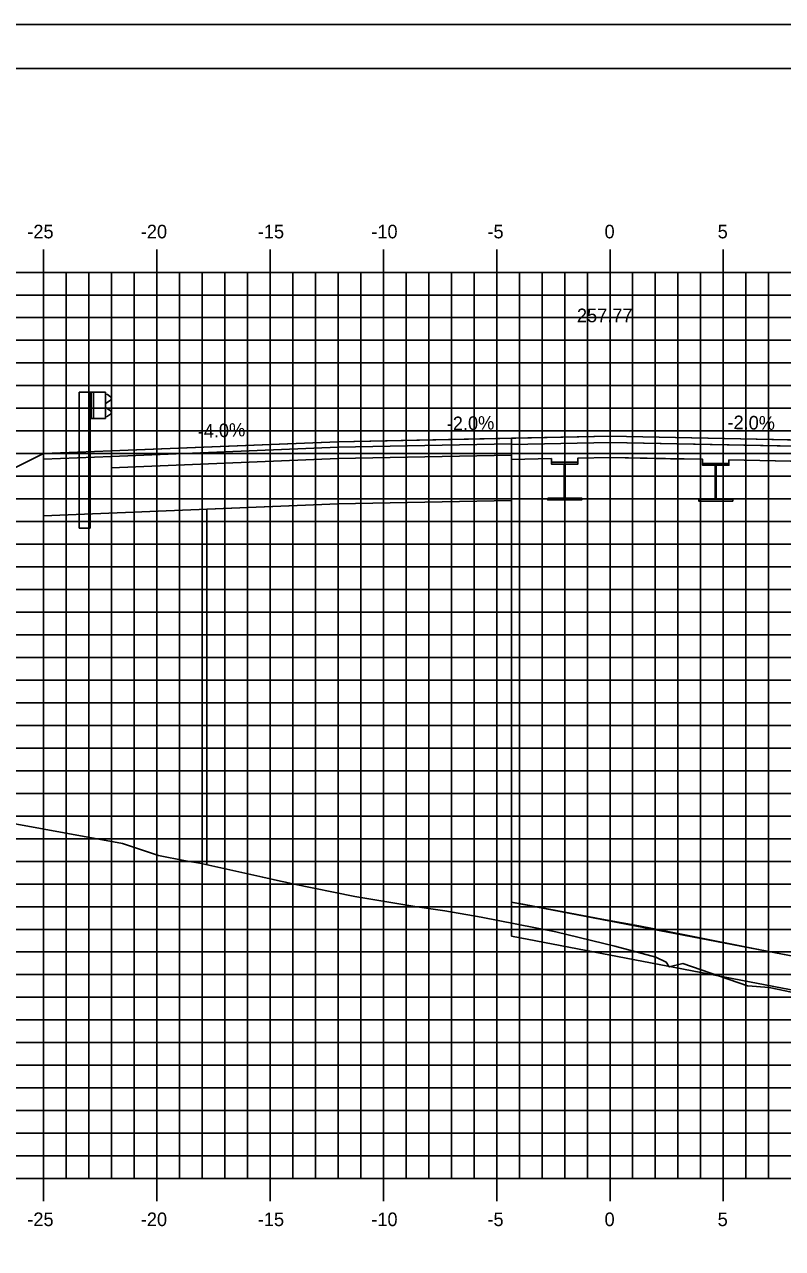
# Model space of a CAD drawing. Extents: x -22 to 1480, y -1511 to 8.
# Drawn here: x 700.4 to 733.8, y -128.6 to -74.5 of the extents above; entities that cross this region are included whole.
import ezdxf

# ---------------------------------------------------------------- set-up
doc = ezdxf.new("R2010")
doc.units = 0
for name, color, linetype in [('ANNOTATION', 7, 'Continuous'), ('BORDER', 7, 'Continuous'), ('D_Bridge_Superstructure', 7, 'Continuous'), ('D_Bridge_Superstructure_Slab', 7, 'Continuous'), ('D_Bridge_Wingwall', 7, 'Continuous'), ('D_Guardrail_Beam_Rt', 7, 'Continuous'), ('D_Roadway_Centerline', 7, 'Continuous'), ('D_Roadway_Centerline_Text', 7, 'Continuous'), ('D_Roadway_Edge_Shoulder', 7, 'Continuous'), ('D_Roadway_Edge_TW', 7, 'Continuous'), ('D_Roadway_Pavement', 7, 'Continuous'), ('D_Roadway_SlopeLines', 7, 'Continuous'), ('D_Roadway_SubGrade', 7, 'Continuous'), ('H_V ANNOTATION', 7, 'Continuous'), ('MAJOR', 7, 'Continuous'), ('MINOR', 7, 'Continuous'), ('PLOT BOUNDARY', 7, 'Continuous'), ('S_Roadway_Centerline', 7, 'Continuous')]:
    doc.layers.add(name, color=color, linetype=linetype)

msp = doc.modelspace()

# ---------------------------------------------------------------- linework, layer by layer
at = {"layer": 'BORDER'}
msp.add_line((811.209, -76.466), (651.209, -76.466), dxfattribs=at)
at = {"layer": 'D_Bridge_Superstructure'}
for p, q in [((724.792, -93.844), (723.626, -93.844)), ((723.626, -93.844), (723.626, -93.928)), ((724.23, -93.928), (724.188, -93.928)), ((724.23, -93.928), (724.188, -93.928)), ((724.23, -93.928), (724.792, -93.928)), ((724.792, -93.928), (724.792, -93.844)), ((731.459, -93.898), (730.292, -93.898)), ((730.292, -93.898), (730.292, -93.981)), ((730.897, -93.981), (730.855, -93.981)), ((730.897, -93.981), (730.855, -93.981)), ((730.897, -93.981), (731.459, -93.981)), ((731.459, -93.981), (731.459, -93.898)), ((724.188, -95.428), (723.459, -95.428)), ((723.459, -95.428), (723.459, -95.511)), ((724.188, -95.428), (723.459, -95.428)), ((724.23, -95.428), (724.188, -95.428)), ((724.23, -95.428), (724.188, -95.428)), ((730.855, -95.481), (730.126, -95.481)), ((730.126, -95.481), (730.126, -95.564)), ((730.855, -95.481), (730.126, -95.481)), ((730.897, -95.481), (730.855, -95.481)), ((730.897, -95.481), (730.855, -95.481))]:
    msp.add_line(p, q, dxfattribs=at)
for points in [[(723.626, -93.844), (724.792, -93.844), (724.792, -93.928), (723.626, -93.928)], [(724.188, -93.928), (724.23, -93.928), (724.23, -95.428), (724.188, -95.428)], [(730.292, -93.898), (731.459, -93.898), (731.459, -93.981), (730.292, -93.981)], [(730.855, -93.981), (730.897, -93.981), (730.897, -95.481), (730.855, -95.481)], [(723.459, -95.428), (724.959, -95.428), (724.959, -95.511), (723.459, -95.511)], [(730.126, -95.481), (731.626, -95.481), (731.626, -95.564), (730.126, -95.564)]]:
    msp.add_lwpolyline(points, close=True, dxfattribs=at)
for points in [[(724.23, -93.928), (724.792, -93.928), (724.792, -93.844), (723.626, -93.844), (723.626, -93.928), (724.188, -93.928), (724.23, -93.928)], [(723.626, -93.928), (724.188, -93.928), (724.23, -93.928)], [(724.188, -93.928), (724.188, -95.428), (724.23, -95.428), (724.23, -93.928)], [(724.188, -93.928), (724.188, -95.428), (724.23, -95.428), (724.23, -93.928)], [(730.897, -93.981), (731.459, -93.981), (731.459, -93.898), (730.292, -93.898), (730.292, -93.981), (730.855, -93.981), (730.897, -93.981)], [(730.292, -93.981), (730.855, -93.981), (730.897, -93.981)], [(730.855, -93.981), (730.855, -95.481), (730.897, -95.481), (730.897, -93.981)], [(730.855, -93.981), (730.855, -95.481), (730.897, -95.481), (730.897, -93.981)], [(723.459, -95.428), (723.459, -95.511), (724.959, -95.511), (724.959, -95.428), (724.23, -95.428)], [(723.459, -95.511), (724.959, -95.511), (724.959, -95.428), (724.23, -95.428)], [(730.126, -95.481), (730.126, -95.564), (731.626, -95.564), (731.626, -95.481), (730.897, -95.481)], [(730.126, -95.564), (731.626, -95.564), (731.626, -95.481), (730.897, -95.481)]]:
    msp.add_lwpolyline(points, dxfattribs=at)
at = {"layer": 'D_Bridge_Superstructure_Slab'}
msp.add_line((726.209, -93.638), (726.209, -93.638), dxfattribs=at)
for points in [[(721.855, -92.787), (726.209, -92.7), (744.231, -93.061), (744.209, -93.331), (726.209, -92.971), (721.855, -93.058)], [(745.376, -93.354), (726.209, -92.971), (721.855, -93.058)], [(745.376, -93.354), (726.209, -92.971), (721.855, -93.058)], [(721.855, -93.725), (723.626, -93.689), (723.626, -93.844), (724.792, -93.844), (724.792, -93.666), (726.209, -93.638), (727.542, -93.664), (728.876, -93.691), (730.292, -93.719), (730.292, -93.898), (731.459, -93.898), (731.459, -93.743), (735.542, -93.824)], [(723.626, -93.689), (721.855, -93.725)], [(724.792, -93.666), (724.792, -93.844), (723.626, -93.844), (723.626, -93.689)], [(730.292, -93.719), (726.209, -93.638), (724.792, -93.666)], [(730.292, -93.719), (730.292, -93.898), (731.459, -93.898), (731.459, -93.743)], [(736.959, -93.853), (731.459, -93.743)]]:
    msp.add_lwpolyline(points, dxfattribs=at)
at = {"layer": 'D_Bridge_Wingwall'}
msp.add_lwpolyline([(721.855, -114.194), (721.855, -95.537), (714.209, -95.69), (708.412, -95.922), (708.412, -111.617)], dxfattribs=at)
at = {"layer": 'D_Guardrail_Beam_Rt'}
for p, q in [((702.78, -90.757), (702.78, -96.757)), ((703.25, -90.757), (702.78, -90.757)), ((703.938, -90.757), (703.25, -90.757)), ((703.25, -90.757), (703.25, -91.923)), ((703.313, -90.757), (703.313, -91.923)), ((703.417, -90.757), (703.417, -91.923)), ((703.938, -91.923), (703.938, -90.757)), ((703.938, -90.84), (704.012, -90.855)), ((703.942, -91.305), (703.942, -91.375)), ((704.171, -91.104), (703.976, -91.241)), ((704.028, -90.861), (704.171, -90.961)), ((704.012, -91.826), (703.938, -91.84)), ((703.976, -91.44), (704.171, -91.576)), ((704.171, -91.719), (704.028, -91.819)), ((703.25, -91.923), (703.938, -91.923)), ((703.271, -96.757), (703.271, -91.923)), ((703.271, -96.757), (702.78, -96.757))]:
    msp.add_line(p, q, dxfattribs=at)
for centre, major_axis, start_param, end_param in [((704.021, -91.305), (-0.0789, 0), 5.323254, 6.283185), ((704.004, -90.895), (0.0417, 0), 0.959931, 1.376053), ((704.121, -91.033), (0.0877, 0), 5.323254, 7.243116), ((704.021, -91.375), (-0.0789, 0), 6.283185, 7.243116), ((704.004, -91.785), (0.0417, 0), 4.907132, 5.323254), ((704.121, -91.647), (0.0877, 0), 5.323254, 7.243116)]:
    msp.add_ellipse(centre, major_axis=major_axis, ratio=0.995501, start_param=start_param, end_param=end_param, dxfattribs=at)
at = {"layer": 'D_Roadway_Centerline'}
msp.add_line((701.209, -93.46), (697.091, -95.519), dxfattribs=at)
for points in [[(701.209, -93.46), (702.709, -93.4), (704.209, -93.34), (709.009, -93.148), (714.209, -92.94), (719.969, -92.825), (726.209, -92.7), (731.969, -92.815), (738.209, -92.94), (739.835, -92.973), (742.467, -93.025), (743.371, -93.043), (744.231, -93.061)], [(721.855, -113.261), (722.095, -113.306), (722.193, -113.324), (725.854, -114.013), (727.479, -114.318), (729.585, -114.73), (732.765, -115.352), (734.514, -115.697), (738.052, -115.435), (739.911, -115.297), (743.338, -115.044), (745.011, -114.942), (748.624, -114.722), (748.947, -114.702), (749.89, -114.645), (752.884, -114.754), (753.911, -114.789), (756.909, -114.855), (759.197, -114.913), (763.898, -115.022), (764.484, -115.034), (765.554, -115.061), (769.77, -115.176)]]:
    msp.add_lwpolyline(points, dxfattribs=at)
at = {"layer": 'D_Roadway_Edge_Shoulder'}
msp.add_lwpolyline([(714.209, -92.94), (704.209, -93.34), (704.209, -93.34), (701.209, -93.46), (701.209, -93.71), (704.209, -93.59), (704.209, -93.59), (714.209, -93.19)], close=True, dxfattribs=at)
at = {"layer": 'D_Roadway_Edge_TW'}
msp.add_lwpolyline([(721.855, -92.787), (714.209, -92.94), (714.209, -93.19), (721.855, -93.037)], dxfattribs=at)
at = {"layer": 'D_Roadway_Pavement'}
msp.add_lwpolyline([(714.209, -93.19), (704.209, -93.59), (704.209, -93.59), (704.209, -94.09), (714.209, -93.69), (714.209, -93.19)], dxfattribs=at)
at = {"layer": 'D_Roadway_SlopeLines'}
msp.add_lwpolyline([(749.89, -114.645), (734.514, -115.697), (721.855, -113.261), (721.855, -114.761), (734.514, -117.197), (749.89, -116.145)], close=True, dxfattribs=at)
msp.add_lwpolyline([(734.514, -115.697), (721.855, -113.261)], dxfattribs=at)
msp.add_lwpolyline([(734.514, -115.697), (721.855, -113.261)], dxfattribs=at)
at = {"layer": 'D_Roadway_SubGrade'}
msp.add_line((721.855, -95.537), (721.855, -92.787), dxfattribs=at)
msp.add_lwpolyline([(714.209, -93.69), (704.209, -94.09), (704.209, -93.59), (701.209, -93.71), (701.209, -93.46), (701.209, -96.21), (714.209, -95.69)], close=True, dxfattribs=at)
msp.add_lwpolyline([(721.855, -93.537), (714.209, -93.69), (714.209, -95.69), (721.855, -95.537)], dxfattribs=at)
at = {"layer": 'MAJOR'}
for p, q in [((701.209, -84.464), (701.209, -85.466)), ((706.209, -84.464), (706.209, -85.466)), ((711.209, -84.464), (711.209, -85.466)), ((716.209, -84.464), (716.209, -85.466)), ((721.209, -84.464), (721.209, -85.466)), ((726.209, -84.464), (726.209, -85.466)), ((731.209, -84.464), (731.209, -85.466)), ((656.209, -85.466), (796.209, -85.466)), ((656.209, -85.466), (796.209, -85.466)), ((701.209, -125.466), (701.209, -85.466)), ((706.209, -125.466), (706.209, -85.466)), ((711.209, -125.466), (711.209, -85.466)), ((716.209, -125.466), (716.209, -85.466)), ((721.209, -125.466), (721.209, -85.466)), ((726.209, -125.466), (726.209, -85.466)), ((731.209, -125.466), (731.209, -85.466)), ((656.209, -90.466), (796.209, -90.466)), ((656.209, -95.466), (796.209, -95.466)), ((656.209, -100.466), (796.209, -100.466)), ((656.209, -105.466), (796.209, -105.466)), ((656.209, -110.466), (796.209, -110.466)), ((656.209, -115.466), (796.209, -115.466)), ((656.209, -120.466), (796.209, -120.466)), ((656.209, -125.466), (796.209, -125.466)), ((656.209, -125.466), (796.209, -125.466)), ((701.209, -126.468), (701.209, -125.466)), ((706.209, -126.468), (706.209, -125.466)), ((711.209, -126.468), (711.209, -125.466)), ((716.209, -126.468), (716.209, -125.466)), ((721.209, -126.468), (721.209, -125.466)), ((726.209, -126.468), (726.209, -125.466)), ((731.209, -126.468), (731.209, -125.466))]:
    msp.add_line(p, q, dxfattribs=at)
at = {"layer": 'MINOR'}
for p, q in [((702.209, -125.466), (702.209, -85.466)), ((703.209, -125.466), (703.209, -85.466)), ((704.209, -125.466), (704.209, -85.466)), ((705.209, -125.466), (705.209, -85.466)), ((707.209, -125.466), (707.209, -85.466)), ((708.209, -125.466), (708.209, -85.466)), ((709.209, -125.466), (709.209, -85.466)), ((710.209, -125.466), (710.209, -85.466)), ((712.209, -125.466), (712.209, -85.466)), ((713.209, -125.466), (713.209, -85.466)), ((714.209, -125.466), (714.209, -85.466)), ((715.209, -125.466), (715.209, -85.466)), ((717.209, -125.466), (717.209, -85.466)), ((718.209, -125.466), (718.209, -85.466)), ((719.209, -125.466), (719.209, -85.466)), ((720.209, -125.466), (720.209, -85.466)), ((722.209, -125.466), (722.209, -85.466)), ((723.209, -125.466), (723.209, -85.466)), ((724.209, -125.466), (724.209, -85.466)), ((725.209, -125.466), (725.209, -85.466)), ((727.209, -125.466), (727.209, -85.466)), ((728.209, -125.466), (728.209, -85.466)), ((729.209, -125.466), (729.209, -85.466)), ((730.209, -125.466), (730.209, -85.466)), ((732.209, -125.466), (732.209, -85.466)), ((733.209, -125.466), (733.209, -85.466)), ((656.209, -86.466), (796.209, -86.466)), ((656.209, -87.466), (796.209, -87.466)), ((656.209, -88.466), (796.209, -88.466)), ((656.209, -89.466), (796.209, -89.466)), ((656.209, -91.466), (796.209, -91.466)), ((656.209, -92.466), (796.209, -92.466)), ((656.209, -93.466), (796.209, -93.466)), ((656.209, -94.466), (796.209, -94.466)), ((656.209, -96.466), (796.209, -96.466)), ((656.209, -97.466), (796.209, -97.466)), ((656.209, -98.466), (796.209, -98.466)), ((656.209, -99.466), (796.209, -99.466)), ((656.209, -101.466), (796.209, -101.466)), ((656.209, -102.466), (796.209, -102.466)), ((656.209, -103.466), (796.209, -103.466)), ((656.209, -104.466), (796.209, -104.466)), ((656.209, -106.466), (796.209, -106.466)), ((656.209, -107.466), (796.209, -107.466)), ((656.209, -108.466), (796.209, -108.466)), ((656.209, -109.466), (796.209, -109.466)), ((656.209, -111.466), (796.209, -111.466)), ((656.209, -112.466), (796.209, -112.466)), ((656.209, -113.466), (796.209, -113.466)), ((656.209, -114.466), (796.209, -114.466)), ((656.209, -116.466), (796.209, -116.466)), ((656.209, -117.466), (796.209, -117.466)), ((656.209, -118.466), (796.209, -118.466)), ((656.209, -119.466), (796.209, -119.466)), ((656.209, -121.466), (796.209, -121.466)), ((656.209, -122.466), (796.209, -122.466)), ((656.209, -123.466), (796.209, -123.466)), ((656.209, -124.466), (796.209, -124.466))]:
    msp.add_line(p, q, dxfattribs=at)
at = {"layer": 'PLOT BOUNDARY'}
msp.add_lwpolyline([(643.116, -184.525), (813.116, -184.525), (813.116, -74.525), (643.116, -74.525)], close=True, dxfattribs=at)
at = {"layer": 'S_Roadway_Centerline'}
msp.add_lwpolyline([(698.805, -109.607), (704.7, -110.677), (706.283, -111.214), (707.472, -111.446), (708.102, -111.548), (710.885, -112.166), (711.669, -112.339), (711.887, -112.384), (712.204, -112.451), (714.949, -113.013), (717.6, -113.464), (718.915, -113.656), (720.525, -113.934), (722.095, -114.24), (723.824, -114.581), (726.42, -115.208), (728.236, -115.688), (728.692, -115.914), (728.826, -116.127), (729.43, -115.976), (732.283, -116.955), (732.288, -116.955), (733.228, -117.038), (734.568, -117.311)], dxfattribs=at)

# ---------------------------------------------------------------- texts
at = {"layer": 'ANNOTATION'}
for s, rotation, p in [('-2.0%', 1.1458, (719.012, -92.444)), ('-2.0%', 358.8542, (731.386, -92.38)), ('-4.0%', 2.2906, (708.025, -92.787))]:
    msp.add_text(s, height=0.6, rotation=rotation, dxfattribs=at).set_placement(p)
at = {"layer": 'D_Roadway_Centerline'}
for s, p in [('C', (726.204, -92.7)), ('L', (726.209, -92.707))]:
    msp.add_text(s, height=0.0146, dxfattribs=at).set_placement(p)
at = {"layer": 'D_Roadway_Centerline_Text'}
msp.add_text('257.77', height=0.6, dxfattribs=at).set_placement((724.748, -87.668))
at = {"layer": 'H_V ANNOTATION'}
for s, p in [('-25', (700.494, -83.966)), ('-20', (705.502, -83.966)), ('-15', (710.666, -83.966)), ('-10', (715.674, -83.966)), ('-5', (720.799, -83.966)), ('0', (725.968, -83.966)), ('5', (730.96, -83.966)), ('-25', (700.494, -127.566)), ('-20', (705.502, -127.566)), ('-15', (710.666, -127.566)), ('-10', (715.674, -127.566)), ('-5', (720.799, -127.566)), ('0', (725.968, -127.566)), ('5', (730.96, -127.566))]:
    msp.add_text(s, height=0.6, dxfattribs=at).set_placement(p)

doc.saveas('drawing.dxf')
